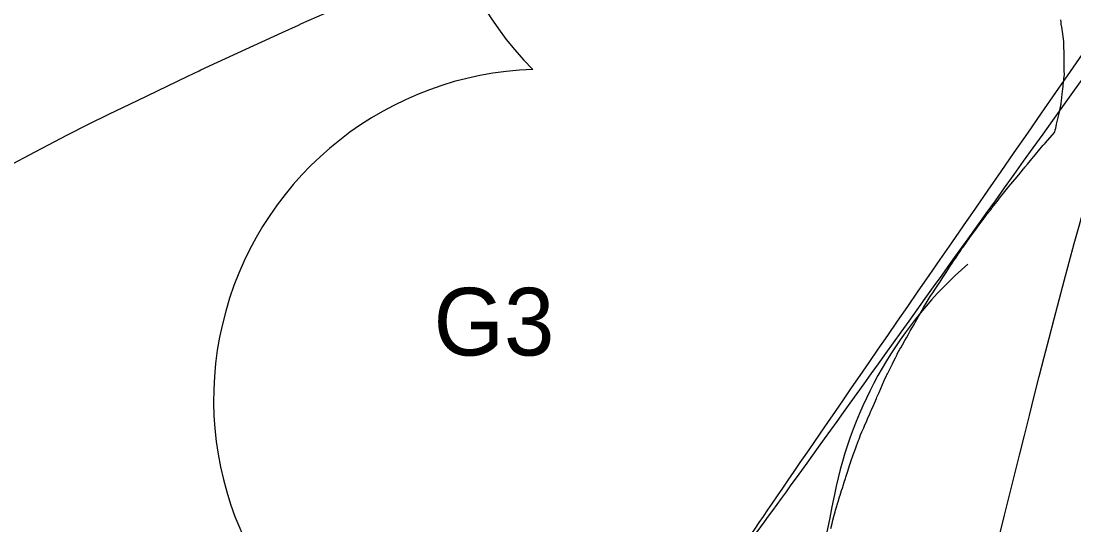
# Model space of a CAD drawing. Extents: x 0 to 512122, y 0 to 6212554.
# Drawn here: x 511655.18 to 511674.62, y 6211434.84 to 6211444.14 of the extents above; entities that cross this region are included whole.
import ezdxf

# ---------------------------------------------------------------- set-up
doc = ezdxf.new("R2010")
doc.units = 0
for name, color, linetype in [('_G3_engræsser', 7, 'Continuous'), ('_G3S_Slået græsser', 7, 'Continuous'), ('_Paths', 7, 'Continuous'), ('_S1_rabarber', 7, 'Continuous'), ('Clouds', 7, 'Continuous'), ('TV_U_AFM_Symbl_Gul', 7, 'Continuous'), ('TV_U_LYS_Nyx330-Trafiksti-x2', 7, 'Continuous')]:
    doc.layers.add(name, color=color, linetype=linetype)

msp = doc.modelspace()

# ---------------------------------------------------------------- linework, layer by layer
at = {"layer": '_G3_engræsser'}
msp.add_arc((511428.115, 6211746.745), 376.469, 304.81194, 307.93028, dxfattribs=at)
at = {"layer": '_G3S_Slået græsser'}
for centre, radius, start, end in [((511677.653, 6211433.926), 7.599, 131.0558, 168.8304), ((511736.39, 6211421.612), 67.612, 168.23466, 174.58303)]:
    msp.add_arc(centre, radius, start, end, dxfattribs=at)
at = {"layer": '_Paths'}
for points, degree in [([(511640.462, 6211394.164), (511666.005, 6211408.809), (511672.517, 6211429.483), (511676.559, 6211451.282), (511690.481, 6211465.664), (511705.077, 6211478.474), (511709.825, 6211494.014), (511640.462, 6211394.164), (511709.825, 6211494.014)], 3), ([(511651.32, 6211395.399), (511670.02, 6211402.099), (511675.836, 6211429.41), (511675.931, 6211450.773), (511691.497, 6211463.947), (511708.899, 6211474.665), (511711.288, 6211488), (511712.286, 6211493.573)], 2)]:
    msp.add_open_spline(points, degree=degree, dxfattribs=at)
at = {"layer": '_S1_rabarber'}
msp.add_open_spline([(511659.815, 6211399.937), (511668.561, 6211404.361), (511673.198, 6211404.114), (511679.922, 6211414.023), (511688.007, 6211417.394), (511690.187, 6211425.291), (511687.866, 6211432.031), (511684.336, 6211437.489), (511684.603, 6211441.593), (511684.719, 6211443.38)], degree=3, dxfattribs=at)
msp.add_open_spline([(511659.815, 6211399.937), (511668.561, 6211404.361), (511673.198, 6211404.114), (511679.922, 6211414.023), (511688.007, 6211417.394), (511690.187, 6211425.291), (511687.866, 6211432.031), (511684.336, 6211437.489), (511684.603, 6211441.593), (511684.719, 6211443.38)], degree=3, dxfattribs=at)
at = {"layer": 'Clouds'}
for centre, radius, start, end in [((511668.957, 6211447.548), 6.1, 79.802, 224.802), ((511664.837, 6211437.153), 6.101, 91.9555, 236.9555)]:
    msp.add_arc(centre, radius, start, end, dxfattribs=at)
at = {"layer": 'TV_U_LYS_Nyx330-Trafiksti-x2'}
for points in [[(511654.933, 6211441.456), (511655.441, 6211441.727), (511655.919, 6211441.982), (511656.027, 6211442.036), (511656.427, 6211442.237), (511656.813, 6211442.431), (511657.189, 6211442.611), (511657.507, 6211442.764), (511658.263, 6211443.127), (511658.467, 6211443.225), (511658.503, 6211443.242), (511658.807, 6211443.383), (511659.999, 6211443.93), (511660.302, 6211444.069), (511660.361, 6211444.096), (511660.925, 6211444.347)], [(511674.369, 6211444.166), (511674.375, 6211444.121), (511674.377, 6211444.105), (511674.379, 6211444.089), (511674.387, 6211444.032), (511674.405, 6211443.906), (511674.411, 6211443.859), (511674.424, 6211443.766), (511674.427, 6211443.745), (511674.428, 6211443.688), (511674.428, 6211443.642), (511674.429, 6211443.588), (511674.431, 6211443.473), (511674.433, 6211443.342), (511674.434, 6211443.225), (511674.435, 6211443.159), (511674.426, 6211443.078), (511674.424, 6211443.06), (511674.419, 6211443.012), (511674.414, 6211442.967), (511674.411, 6211442.938), (511674.406, 6211442.89), (511674.395, 6211442.792), (511674.382, 6211442.669), (511674.378, 6211442.633), (511674.375, 6211442.605), (511674.37, 6211442.583), (511674.358, 6211442.53), (511674.344, 6211442.467), (511674.338, 6211442.439), (511674.332, 6211442.415), (511674.298, 6211442.263), (511674.293, 6211442.241), (511674.275, 6211442.16), (511674.268, 6211442.128), (511674.26, 6211442.094), (511674.26, 6211442.092), (511674.255, 6211442.087), (511674.087, 6211441.892), (511674.07, 6211441.873), (511674.06, 6211441.862)], [(511670.128, 6211434.77), (511670.153, 6211434.867), (511670.169, 6211434.925), (511670.187, 6211434.991), (511670.211, 6211435.081), (511670.219, 6211435.113), (511670.239, 6211435.186), (511670.247, 6211435.212), (511670.26, 6211435.254), (511670.264, 6211435.265), (511670.293, 6211435.358), (511670.303, 6211435.388), (511670.329, 6211435.471), (511670.344, 6211435.519), (511670.35, 6211435.536), (511670.357, 6211435.559), (511670.379, 6211435.628), (511670.4, 6211435.695), (511670.409, 6211435.723), (511670.443, 6211435.832), (511670.456, 6211435.872), (511670.481, 6211435.953), (511670.491, 6211435.983), (511670.493, 6211435.988), (511670.502, 6211436.012), (511670.545, 6211436.13), (511670.586, 6211436.242), (511670.593, 6211436.26), (511670.638, 6211436.384), (511670.648, 6211436.409), (511670.653, 6211436.423), (511670.681, 6211436.5), (511670.705, 6211436.555), (511670.737, 6211436.629), (511670.753, 6211436.667), (511670.794, 6211436.762), (511670.809, 6211436.797), (511670.848, 6211436.887), (511670.869, 6211436.936), (511670.882, 6211436.966), (511670.915, 6211437.045), (511670.971, 6211437.172), (511670.982, 6211437.199), (511671.004, 6211437.249), (511671.02, 6211437.286), (511671.083, 6211437.432), (511671.114, 6211437.505), (511671.161, 6211437.599), (511671.166, 6211437.609), (511671.174, 6211437.626), (511671.231, 6211437.741), (511671.266, 6211437.811), (511671.284, 6211437.847), (511671.323, 6211437.925), (511671.328, 6211437.935), (511671.354, 6211437.987), (511671.358, 6211437.996), (511671.406, 6211438.081), (511671.422, 6211438.108), (511671.453, 6211438.163), (511671.499, 6211438.246), (511671.528, 6211438.296), (511671.557, 6211438.347), (511671.598, 6211438.42), (511671.639, 6211438.492), (511671.667, 6211438.541), (511671.694, 6211438.59), (511671.742, 6211438.675), (511671.745, 6211438.679), (511671.748, 6211438.686), (511671.82, 6211438.811), (511671.843, 6211438.853), (511671.906, 6211438.964), (511671.906, 6211438.965), (511671.965, 6211439.054), (511671.978, 6211439.074), (511672.011, 6211439.123), (511672.055, 6211439.191), (511672.118, 6211439.287), (511672.129, 6211439.304), (511672.134, 6211439.312), (511672.198, 6211439.408), (511672.258, 6211439.5), (511672.324, 6211439.601), (511672.342, 6211439.628), (511672.371, 6211439.671), (511672.402, 6211439.72), (511672.429, 6211439.761), (511672.481, 6211439.84), (511672.515, 6211439.891), (511672.534, 6211439.919), (511672.536, 6211439.923), (511672.554, 6211439.948), (511672.571, 6211439.971), (511672.628, 6211440.049), (511672.699, 6211440.146), (511672.733, 6211440.193), (511672.788, 6211440.268), (511672.87, 6211440.38), (511672.926, 6211440.457), (511672.954, 6211440.495), (511672.977, 6211440.526), (511673.004, 6211440.563), (511673.024, 6211440.588), (511673.075, 6211440.654), (511673.094, 6211440.679), (511673.109, 6211440.698), (511673.168, 6211440.774), (511673.2, 6211440.814), (511673.263, 6211440.896), (511673.292, 6211440.933), (511673.322, 6211440.972), (511673.338, 6211440.992), (511673.343, 6211440.998), (511673.393, 6211441.059), (511673.454, 6211441.131), (511673.455, 6211441.133), (511673.456, 6211441.134), (511673.527, 6211441.219), (511673.531, 6211441.225), (511673.599, 6211441.307), (511673.69, 6211441.416), (511673.698, 6211441.426), (511673.713, 6211441.444), (511673.763, 6211441.504), (511673.792, 6211441.539), (511673.844, 6211441.602), (511673.882, 6211441.647), (511673.933, 6211441.709), (511673.964, 6211441.746), (511674.044, 6211441.843), (511674.06, 6211441.862)]]:
    msp.add_lwpolyline(points, dxfattribs=at)

# ---------------------------------------------------------------- texts
at = {"layer": 'TV_U_AFM_Symbl_Gul'}
msp.add_text('G3', height=1.25, dxfattribs=at).set_placement((511662.797, 6211437.967))

doc.saveas('drawing.dxf')
